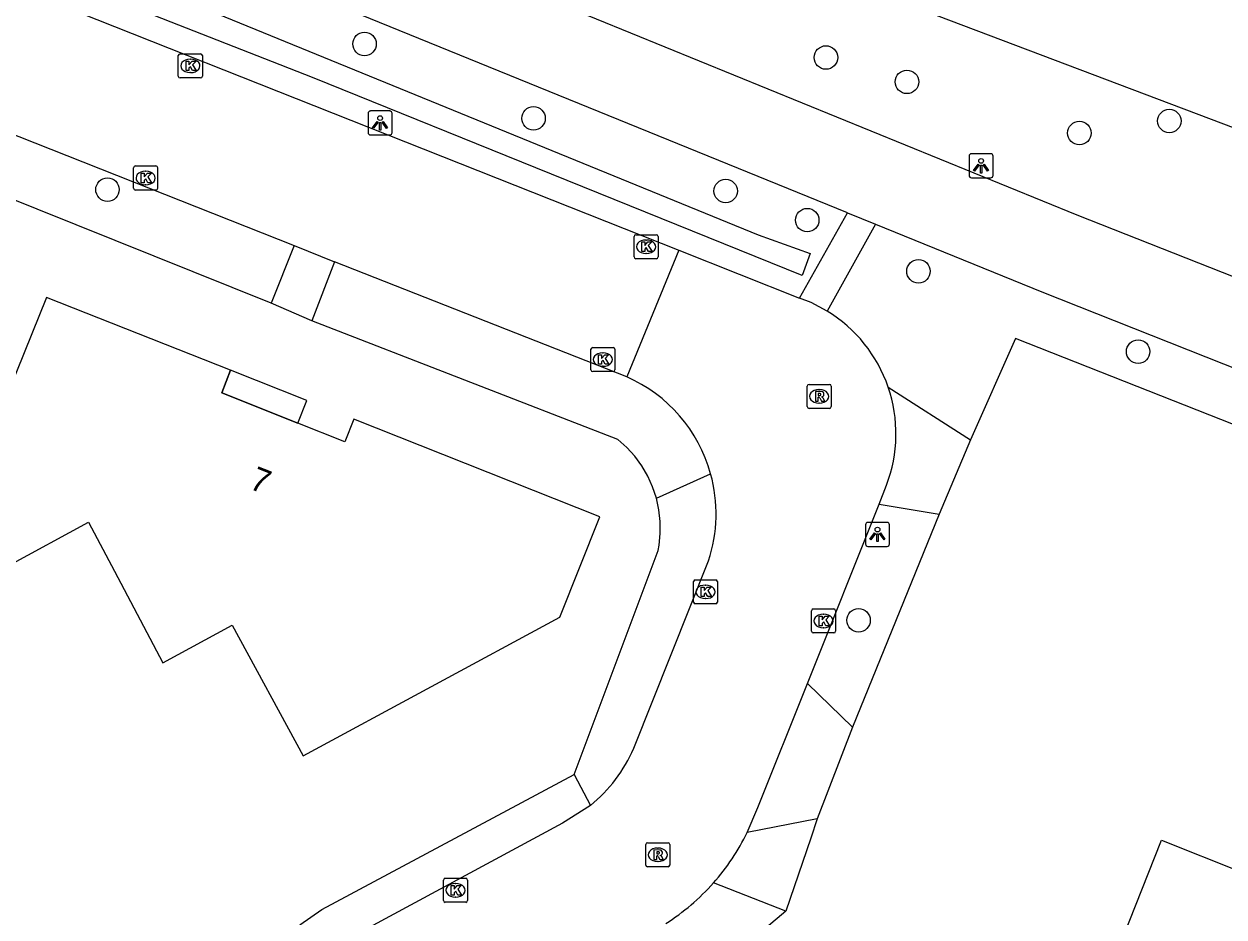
# Model space of a CAD drawing. Extents: x 157321 to 158827, y 386650 to 388532.
# Drawn here: x 158189.75 to 158239.72, y 387285.73 to 387322.9 of the extents above; entities that cross this region are included whole.
import ezdxf

# ---------------------------------------------------------------- set-up
doc = ezdxf.new("R2010")
doc.units = 0
for name, color, linetype in [('IMGEO_Berm_groen', 7, 'Continuous'), ('IMGEO_Boom', 7, 'Continuous'), ('IMGEO_Fietspad_gesloten', 7, 'Continuous'), ('IMGEO_Fietspad_halfverhard', 7, 'Continuous'), ('IMGEO_Greppel_droge_sloot', 7, 'Continuous'), ('IMGEO_Groenvoorziening', 7, 'Continuous'), ('IMGEO_Kolk', 7, 'Continuous'), ('IMGEO_Lichtpunt', 7, 'Continuous'), ('IMGEO_Pand', 7, 'Continuous'), ('IMGEO_Pand_nummerreeks', 7, 'Continuous'), ('IMGEO_Pand_overbouw', 7, 'Continuous'), ('IMGEO_Rijbaan_lokaal_gesloten', 7, 'Continuous'), ('IMGEO_Rioolput', 7, 'Continuous'), ('IMGEO_Voetpad_open', 7, 'Continuous')]:
    doc.layers.add(name, color=color, linetype=linetype)

msp = doc.modelspace()

# ---------------------------------------------------------------- linework, layer by layer
at = {"layer": 'IMGEO_Berm_groen'}
msp.add_lwpolyline([(158278.806, 387307.93), (158276.895, 387304.182), (158265.187, 387309.099), (158221.254, 387325.716), (158222.09, 387328.153)], dxfattribs=at)
at = {"layer": 'IMGEO_Boom'}
for centre in [(158203.934, 387322.067), (158223.145, 387321.502), (158226.519, 387320.489), (158210.971, 387318.97), (158237.443, 387318.86), (158233.699, 387318.359), (158193.23, 387316.004), (158218.971, 387315.946), (158222.367, 387314.735), (158226.999, 387312.606), (158236.145, 387309.262), (158224.505, 387298.08)]:
    msp.add_circle(centre, 0.489, dxfattribs=at)
at = {"layer": 'IMGEO_Fietspad_gesloten'}
for points in [[(158179.894, 387336.819), (158196.427, 387330.121), (158233.586, 387314.953), (158272.994, 387299.418), (158274.047, 387299.005), (158289.751, 387292.854)], [(158224.046, 387315.044), (158195.029, 387326.837), (158178.354, 387333.585)], [(158224.046, 387315.044), (158225.213, 387314.57)], [(158225.213, 387314.57), (158232.134, 387311.757), (158271.569, 387296.126), (158272.304, 387295.835), (158288.418, 387289.45)]]:
    msp.add_lwpolyline(points, dxfattribs=at)
at = {"layer": 'IMGEO_Fietspad_halfverhard'}
for points in [[(158222.051, 387311.493), (158224.046, 387315.044)], [(158225.213, 387314.57), (158223.199, 387310.95)]]:
    msp.add_lwpolyline(points, dxfattribs=at)
at = {"layer": 'IMGEO_Greppel_droge_sloot'}
msp.add_lwpolyline([(158187.304, 387327.627), (158220.325, 387314.118), (158222.485, 387313.349), (158222.156, 387312.434), (158211.722, 387316.644), (158201.765, 387320.671), (158189.611, 387325.448), (158179.141, 387329.549), (158177.31, 387330.226), (158177.749, 387331.214), (158187.304, 387327.627)], dxfattribs=at)
at = {"layer": 'IMGEO_Groenvoorziening'}
for points in [[(158200.048, 387311.279), (158172.43, 387322.36)], [(158216.085, 387303.161), (158215.93, 387303.63), (158215.727, 387304.08), (158215.478, 387304.507), (158215.186, 387304.905), (158214.854, 387305.271), (158214.486, 387305.6), (158201.742, 387310.539)], [(158267.812, 387295.314), (158231.041, 387309.802), (158229.169, 387305.594)], [(158216.085, 387303.161), (158218.345, 387304.178)], [(158212.666, 387291.668), (158216.158, 387300.99), (158216.196, 387301.202), (158216.245, 387301.693), (158216.243, 387302.187), (158216.189, 387302.678), (158216.085, 387303.161)], [(158227.86, 387302.504), (158224.25, 387293.632)], [(158222.786, 387289.814), (158222.515, 387289.017), (158221.481, 387285.976)]]:
    msp.add_lwpolyline(points, dxfattribs=at)
at = {"layer": 'IMGEO_Kolk'}
for p, q in [((158196.254, 387321.655), (158197.106, 387321.655)), ((158196.179, 387320.729), (158196.179, 387321.581)), ((158196.667, 387321.435), (158196.692, 387321.435)), ((158197.18, 387321.581), (158197.18, 387320.729)), ((158197.106, 387320.655), (158196.254, 387320.655)), ((158196.69, 387320.875), (158196.665, 387320.875)), ((158194.318, 387316.061), (158194.318, 387316.913)), ((158194.393, 387316.987), (158195.245, 387316.987)), ((158194.806, 387316.767), (158194.831, 387316.767)), ((158195.319, 387316.913), (158195.319, 387316.061)), ((158194.829, 387316.207), (158194.804, 387316.207)), ((158195.245, 387315.987), (158194.393, 387315.987)), ((158215.158, 387313.201), (158215.158, 387314.053)), ((158215.233, 387314.127), (158216.085, 387314.127)), ((158215.646, 387313.907), (158215.671, 387313.907)), ((158216.159, 387314.053), (158216.159, 387313.201)), ((158215.669, 387313.347), (158215.644, 387313.347)), ((158216.085, 387313.127), (158215.233, 387313.127)), ((158213.358, 387308.507), (158213.358, 387309.359)), ((158213.433, 387309.433), (158214.285, 387309.433)), ((158213.846, 387309.213), (158213.871, 387309.213)), ((158214.359, 387309.359), (158214.359, 387308.507)), ((158213.869, 387308.653), (158213.844, 387308.653)), ((158214.285, 387308.433), (158213.433, 387308.433)), ((158217.629, 387298.839), (158217.629, 387299.691)), ((158217.704, 387299.765), (158218.556, 387299.765)), ((158218.63, 387299.691), (158218.63, 387298.839)), ((158218.117, 387299.545), (158218.142, 387299.545)), ((158218.556, 387298.765), (158217.704, 387298.765)), ((158218.14, 387298.985), (158218.115, 387298.985)), ((158222.545, 387297.627), (158222.545, 387298.479)), ((158222.62, 387298.553), (158223.472, 387298.553)), ((158223.033, 387298.333), (158223.058, 387298.333)), ((158223.546, 387298.479), (158223.546, 387297.627)), ((158223.056, 387297.773), (158223.031, 387297.773)), ((158223.472, 387297.553), (158222.62, 387297.553)), ((158207.22, 387286.417), (158207.22, 387287.269)), ((158207.295, 387287.343), (158208.147, 387287.343)), ((158208.221, 387287.269), (158208.221, 387286.417)), ((158207.708, 387287.123), (158207.733, 387287.123)), ((158208.147, 387286.343), (158207.295, 387286.343)), ((158207.731, 387286.563), (158207.706, 387286.563))]:
    msp.add_line(p, q, dxfattribs=at)
for points in [[(158196.254, 387321.655), (158197.106, 387321.655)], [(158196.179, 387320.729), (158196.179, 387321.581)], [(158196.5, 387321.355), (158196.623, 387321.355), (158196.623, 387321.204), (158196.753, 387321.355), (158196.917, 387321.355), (158196.771, 387321.204), (158196.924, 387320.955), (158196.772, 387320.955), (158196.687, 387321.119), (158196.623, 387321.052), (158196.623, 387320.955), (158196.5, 387320.955), (158196.5, 387321.355)], [(158197.18, 387321.581), (158197.18, 387320.729)], [(158197.106, 387320.655), (158196.254, 387320.655)], [(158194.318, 387316.061), (158194.318, 387316.913)], [(158194.393, 387316.987), (158195.245, 387316.987)], [(158194.639, 387316.687), (158194.762, 387316.687), (158194.762, 387316.536), (158194.892, 387316.687), (158195.056, 387316.687), (158194.91, 387316.536), (158195.063, 387316.287), (158194.911, 387316.287), (158194.826, 387316.451), (158194.762, 387316.384), (158194.762, 387316.287), (158194.639, 387316.287), (158194.639, 387316.687)], [(158195.319, 387316.913), (158195.319, 387316.061)], [(158195.245, 387315.987), (158194.393, 387315.987)], [(158215.158, 387313.201), (158215.158, 387314.053)], [(158215.233, 387314.127), (158216.085, 387314.127)], [(158215.479, 387313.827), (158215.602, 387313.827), (158215.602, 387313.676), (158215.732, 387313.827), (158215.896, 387313.827), (158215.75, 387313.676), (158215.903, 387313.427), (158215.751, 387313.427), (158215.666, 387313.591), (158215.602, 387313.524), (158215.602, 387313.427), (158215.479, 387313.427), (158215.479, 387313.827)], [(158216.159, 387314.053), (158216.159, 387313.201)], [(158216.085, 387313.127), (158215.233, 387313.127)], [(158213.358, 387308.507), (158213.358, 387309.359)], [(158213.433, 387309.433), (158214.285, 387309.433)], [(158214.359, 387309.359), (158214.359, 387308.507)], [(158213.679, 387309.133), (158213.802, 387309.133), (158213.802, 387308.982), (158213.932, 387309.133), (158214.096, 387309.133), (158213.95, 387308.982), (158214.103, 387308.733), (158213.951, 387308.733), (158213.866, 387308.897), (158213.802, 387308.83), (158213.802, 387308.733), (158213.679, 387308.733), (158213.679, 387309.133)], [(158214.285, 387308.433), (158213.433, 387308.433)], [(158217.629, 387298.839), (158217.629, 387299.691)], [(158217.704, 387299.765), (158218.556, 387299.765)], [(158218.63, 387299.691), (158218.63, 387298.839)], [(158217.95, 387299.465), (158218.073, 387299.465), (158218.073, 387299.314), (158218.203, 387299.465), (158218.367, 387299.465), (158218.221, 387299.314), (158218.374, 387299.065), (158218.222, 387299.065), (158218.137, 387299.229), (158218.073, 387299.162), (158218.073, 387299.065), (158217.95, 387299.065), (158217.95, 387299.465)], [(158218.556, 387298.765), (158217.704, 387298.765)], [(158222.545, 387297.627), (158222.545, 387298.479)], [(158222.62, 387298.553), (158223.472, 387298.553)], [(158222.866, 387298.253), (158222.989, 387298.253), (158222.989, 387298.102), (158223.119, 387298.253), (158223.283, 387298.253), (158223.137, 387298.102), (158223.29, 387297.853), (158223.138, 387297.853), (158223.053, 387298.017), (158222.989, 387297.95), (158222.989, 387297.853), (158222.866, 387297.853), (158222.866, 387298.253)], [(158223.546, 387298.479), (158223.546, 387297.627)], [(158223.472, 387297.553), (158222.62, 387297.553)], [(158207.22, 387286.417), (158207.22, 387287.269)], [(158207.295, 387287.343), (158208.147, 387287.343)], [(158208.221, 387287.269), (158208.221, 387286.417)], [(158207.541, 387287.043), (158207.664, 387287.043), (158207.664, 387286.892), (158207.794, 387287.043), (158207.958, 387287.043), (158207.812, 387286.892), (158207.965, 387286.643), (158207.813, 387286.643), (158207.728, 387286.807), (158207.664, 387286.74), (158207.664, 387286.643), (158207.541, 387286.643), (158207.541, 387287.043)], [(158208.147, 387286.343), (158207.295, 387286.343)]]:
    msp.add_lwpolyline(points, dxfattribs=at)
for centre, start, end in [((158196.256, 387321.579), 91.552, 178.448), ((158196.256, 387321.579), 91.552, 178.448), ((158197.104, 387321.579), 1.552, 88.448), ((158197.104, 387321.579), 1.552, 88.448), ((158196.256, 387320.731), 181.552, 268.448), ((158196.256, 387320.731), 181.552, 268.448), ((158197.104, 387320.731), 271.552, 358.448), ((158197.104, 387320.731), 271.552, 358.448), ((158194.395, 387316.911), 91.552, 178.448), ((158194.395, 387316.911), 91.552, 178.448), ((158195.243, 387316.911), 1.552, 88.448), ((158195.243, 387316.911), 1.552, 88.448), ((158194.395, 387316.063), 181.552, 268.448), ((158194.395, 387316.063), 181.552, 268.448), ((158195.243, 387316.063), 271.552, 358.448), ((158195.243, 387316.063), 271.552, 358.448), ((158215.235, 387314.051), 91.552, 178.448), ((158215.235, 387314.051), 91.552, 178.448), ((158216.083, 387314.051), 1.552, 88.448), ((158216.083, 387314.051), 1.552, 88.448), ((158215.235, 387313.203), 181.552, 268.448), ((158215.235, 387313.203), 181.552, 268.448), ((158216.083, 387313.203), 271.552, 358.448), ((158216.083, 387313.203), 271.552, 358.448), ((158213.435, 387309.357), 91.552, 178.448), ((158213.435, 387309.357), 91.552, 178.448), ((158214.283, 387309.357), 1.552, 88.448), ((158214.283, 387309.357), 1.552, 88.448), ((158213.435, 387308.509), 181.552, 268.448), ((158213.435, 387308.509), 181.552, 268.448), ((158214.283, 387308.509), 271.552, 358.448), ((158214.283, 387308.509), 271.552, 358.448), ((158217.706, 387299.689), 91.552, 178.448), ((158217.706, 387299.689), 91.552, 178.448), ((158218.554, 387299.689), 1.552, 88.448), ((158218.554, 387299.689), 1.552, 88.448), ((158217.706, 387298.841), 181.552, 268.448), ((158217.706, 387298.841), 181.552, 268.448), ((158218.554, 387298.841), 271.552, 358.448), ((158218.554, 387298.841), 271.552, 358.448), ((158222.622, 387298.477), 91.552, 178.448), ((158222.622, 387298.477), 91.552, 178.448), ((158223.47, 387298.477), 1.552, 88.448), ((158223.47, 387298.477), 1.552, 88.448), ((158222.622, 387297.629), 181.552, 268.448), ((158222.622, 387297.629), 181.552, 268.448), ((158223.47, 387297.629), 271.552, 358.448), ((158223.47, 387297.629), 271.552, 358.448), ((158207.297, 387287.267), 91.552, 178.448), ((158207.297, 387287.267), 91.552, 178.448), ((158208.145, 387287.267), 1.552, 88.448), ((158208.145, 387287.267), 1.552, 88.448), ((158207.297, 387286.419), 181.552, 268.448), ((158207.297, 387286.419), 181.552, 268.448), ((158208.145, 387286.419), 271.552, 358.448), ((158208.145, 387286.419), 271.552, 358.448)]:
    msp.add_arc(centre, 0.0765, start, end, dxfattribs=at)
for centre, major_axis, ratio, start_param, end_param in [((158196.666, 387321.155), (-0.387, 0.002), 0.722429, 4.712389, 7.853982), ((158196.691, 387321.155), (-0.39, 0.002), 0.717154, 1.570796, 4.712389), ((158194.805, 387316.487), (-0.387, 0.002), 0.722429, 4.712389, 7.853982), ((158194.83, 387316.487), (-0.39, 0.002), 0.717154, 1.570796, 4.712389), ((158215.645, 387313.627), (-0.387, 0.002), 0.722429, 4.712389, 7.853982), ((158215.67, 387313.627), (-0.39, 0.002), 0.717154, 1.570796, 4.712389), ((158213.845, 387308.933), (-0.387, 0.002), 0.722429, 4.712389, 7.853982), ((158213.87, 387308.933), (-0.39, 0.002), 0.717154, 1.570796, 4.712389), ((158218.116, 387299.265), (-0.387, 0.002), 0.722429, 4.712389, 7.853982), ((158218.141, 387299.265), (-0.39, 0.002), 0.717154, 1.570796, 4.712389), ((158223.032, 387298.053), (-0.387, 0.002), 0.722429, 4.712389, 7.853982), ((158223.057, 387298.053), (-0.39, 0.002), 0.717154, 1.570796, 4.712389), ((158207.707, 387286.843), (-0.387, 0.002), 0.722429, 4.712389, 7.853982), ((158207.732, 387286.843), (-0.39, 0.002), 0.717154, 1.570796, 4.712389)]:
    msp.add_ellipse(centre, major_axis=major_axis, ratio=ratio, start_param=start_param, end_param=end_param, dxfattribs=at)
at = {"layer": 'IMGEO_Lichtpunt'}
for p, q in [((158204.082, 387319.181), (158204.082, 387318.374)), ((158204.082, 387319.181), (158204.082, 387318.374)), ((158204.984, 387319.276), (158204.176, 387319.276)), ((158204.984, 387319.276), (158204.176, 387319.276)), ((158205.078, 387318.374), (158205.078, 387319.181)), ((158205.078, 387318.374), (158205.078, 387319.181)), ((158204.176, 387318.28), (158204.984, 387318.28)), ((158204.176, 387318.28), (158204.984, 387318.28)), ((158229.107, 387317.401), (158229.107, 387316.594)), ((158229.107, 387317.401), (158229.107, 387316.594)), ((158230.009, 387317.496), (158229.201, 387317.496)), ((158230.009, 387317.496), (158229.201, 387317.496)), ((158230.103, 387316.594), (158230.103, 387317.401)), ((158230.103, 387316.594), (158230.103, 387317.401)), ((158229.201, 387316.5), (158230.009, 387316.5)), ((158229.201, 387316.5), (158230.009, 387316.5)), ((158225.695, 387302.154), (158224.887, 387302.154)), ((158225.695, 387302.154), (158224.887, 387302.154)), ((158224.793, 387302.059), (158224.793, 387301.252)), ((158224.793, 387302.059), (158224.793, 387301.252)), ((158225.789, 387301.252), (158225.789, 387302.059)), ((158225.789, 387301.252), (158225.789, 387302.059)), ((158224.887, 387301.158), (158225.695, 387301.158)), ((158224.887, 387301.158), (158225.695, 387301.158))]:
    msp.add_line(p, q, dxfattribs=at)
for points in [[(158204.456, 387318.845), (158204.495, 387318.817), (158204.307, 387318.555), (158204.269, 387318.582), (158204.456, 387318.845)], [(158204.558, 387318.797), (158204.605, 387318.797), (158204.605, 387318.475), (158204.558, 387318.475), (158204.558, 387318.797)], [(158204.668, 387318.817), (158204.706, 387318.844), (158204.893, 387318.582), (158204.854, 387318.554), (158204.668, 387318.817)], [(158229.481, 387317.065), (158229.52, 387317.037), (158229.332, 387316.775), (158229.294, 387316.802), (158229.481, 387317.065)], [(158229.583, 387317.017), (158229.63, 387317.017), (158229.63, 387316.695), (158229.583, 387316.695), (158229.583, 387317.017)], [(158229.693, 387317.037), (158229.731, 387317.064), (158229.918, 387316.802), (158229.879, 387316.774), (158229.693, 387317.037)], [(158225.167, 387301.723), (158225.206, 387301.695), (158225.018, 387301.433), (158224.98, 387301.46), (158225.167, 387301.723)], [(158225.269, 387301.675), (158225.316, 387301.675), (158225.316, 387301.353), (158225.269, 387301.353), (158225.269, 387301.675)], [(158225.379, 387301.695), (158225.417, 387301.722), (158225.604, 387301.46), (158225.565, 387301.432), (158225.379, 387301.695)]]:
    msp.add_lwpolyline(points, dxfattribs=at)
for centre in [(158204.581, 387318.979), (158229.606, 387317.199), (158225.292, 387301.857)]:
    msp.add_circle(centre, 0.0994, dxfattribs=at)
for centre, start, end in [((158204.176, 387319.181), 90, 180), ((158204.176, 387319.181), 90, 180), ((158204.984, 387319.181), 0, 90), ((158204.984, 387319.181), 0, 90), ((158204.176, 387318.374), 180, 270), ((158204.176, 387318.374), 180, 270), ((158204.984, 387318.374), 270, 0), ((158204.984, 387318.374), 270, 360), ((158229.201, 387317.401), 90, 180), ((158229.201, 387317.401), 90, 180), ((158230.009, 387317.401), 0, 90), ((158230.009, 387317.401), 0, 90), ((158229.201, 387316.594), 180, 270), ((158229.201, 387316.594), 180, 270), ((158230.009, 387316.594), 270, 0), ((158230.009, 387316.594), 270, 360), ((158224.887, 387302.059), 90, 180), ((158224.887, 387302.059), 90, 180), ((158225.695, 387302.059), 0, 90), ((158225.695, 387302.059), 0, 90), ((158224.887, 387301.252), 180, 270), ((158224.887, 387301.252), 180, 270), ((158225.695, 387301.252), 270, 0), ((158225.695, 387301.252), 270, 360)]:
    msp.add_arc(centre, 0.0946, start, end, dxfattribs=at)
at = {"layer": 'IMGEO_Pand'}
for points in [[(158203.483, 387306.446), (158203.112, 387305.513), (158201.15, 387306.291), (158197.986, 387307.545), (158198.358, 387308.486), (158190.685, 387311.518), (158189.153, 387307.696), (158185.52, 387305.721), (158186.728, 387303.535), (158186.195, 387303.228), (158186.474, 387302.714), (158187.529, 387303.287), (158189.116, 387300.367), (158192.433, 387302.167), (158193.515, 387300.122), (158195.529, 387296.309), (158198.42, 387297.878), (158201.372, 387292.438), (158212.072, 387298.205), (158213.734, 387302.382), (158203.483, 387306.446)], [(158237.116, 387288.93), (158240.464, 387287.604), (158244.111, 387296.805), (158249.488, 387294.684), (158250.355, 387295.05), (158251.933, 387294.404), (158252.607, 387292.838), (158251.998, 387291.256), (158251.148, 387290.862), (158246.289, 387278.719), (158242.857, 387280.086), (158238.212, 387281.937), (158238.581, 387282.865), (158235.239, 387284.197), (158237.116, 387288.93)]]:
    msp.add_lwpolyline(points, dxfattribs=at)
at = {"layer": 'IMGEO_Pand_overbouw'}
msp.add_lwpolyline([(158201.15, 387306.291), (158201.524, 387307.233), (158198.358, 387308.486), (158197.986, 387307.545)], close=True, dxfattribs=at)
at = {"layer": 'IMGEO_Rijbaan_lokaal_gesloten'}
for points in [[(158177.571, 387329.112), (158217.018, 387313.487)], [(158173.33, 387324.641), (158201.008, 387313.673)], [(158201.008, 387313.673), (158202.682, 387313.005)], [(158217.018, 387313.487), (158214.851, 387308.211)], [(158217.018, 387313.487), (158222.051, 387311.493)], [(158214.851, 387308.211), (158202.682, 387313.005)], [(158223.199, 387310.95), (158222.531, 387311.303), (158222.051, 387311.493)], [(158225.358, 387302.918), (158225.666, 387303.699)], [(158222.375, 387295.445), (158225.358, 387302.918)], [(158215.147, 387292.757), (158218.253, 387300.556)], [(158219.872, 387289.252), (158220.307, 387290.283), (158222.375, 387295.445)], [(158213.337, 387290.375), (158212.181, 387289.632), (158203.049, 387284.719), (158202.098, 387284.23)]]:
    msp.add_lwpolyline(points, dxfattribs=at)
for centre, radius, start, end in [((158220.075, 387305.844), 5.986, 18.9435, 58.5438), ((158212.351, 387302.515), 6.221, 15.5066, 66.3016), ((158220.07, 387305.841), 5.991, 339.0548, 18.9552), ((158212.361, 387302.518), 6.21, 341.5853, 15.5046), ((158209.36, 387295.276), 6.312, 309.0614, 336.4787), ((158211.31, 387293.478), 9.548, 318.4893, 333.7289), ((158211.357, 387293.453), 9.496, 302.6484, 318.4158)]:
    msp.add_arc(centre, radius, start, end, dxfattribs=at)
at = {"layer": 'IMGEO_Rioolput'}
for p, q in [((158222.367, 387306.974), (158222.367, 387307.826)), ((158222.442, 387307.9), (158223.294, 387307.9)), ((158222.855, 387307.68), (158222.88, 387307.68)), ((158223.368, 387307.826), (158223.368, 387306.974)), ((158223.294, 387306.9), (158222.442, 387306.9)), ((158222.878, 387307.12), (158222.853, 387307.12)), ((158215.644, 387287.895), (158215.644, 387288.747)), ((158215.719, 387288.821), (158216.571, 387288.821)), ((158216.645, 387288.747), (158216.645, 387287.895)), ((158216.132, 387288.601), (158216.157, 387288.601)), ((158216.571, 387287.821), (158215.719, 387287.821)), ((158216.155, 387288.041), (158216.13, 387288.041))]:
    msp.add_line(p, q, dxfattribs=at)
for points in [[(158222.367, 387306.974), (158222.367, 387307.826)], [(158222.442, 387307.9), (158223.294, 387307.9)], [(158223.368, 387307.826), (158223.368, 387306.974)], [(158222.956, 387307.598), (158222.704, 387307.6), (158222.704, 387307.2)], [(158222.704, 387307.2), (158222.828, 387307.2), (158222.828, 387307.362), (158222.839, 387307.362)], [(158222.882, 387307.519), (158222.828, 387307.519), (158222.828, 387307.438)], [(158222.828, 387307.438), (158222.88, 387307.438)], [(158222.886, 387307.333), (158222.957, 387307.2), (158223.097, 387307.2), (158223.032, 387307.326)], [(158223.294, 387306.9), (158222.442, 387306.9)], [(158215.644, 387287.895), (158215.644, 387288.747)], [(158215.719, 387288.821), (158216.571, 387288.821)], [(158216.645, 387288.747), (158216.645, 387287.895)], [(158216.233, 387288.519), (158215.981, 387288.521), (158215.981, 387288.121)], [(158215.981, 387288.121), (158216.105, 387288.121), (158216.105, 387288.283), (158216.116, 387288.283)], [(158216.159, 387288.44), (158216.105, 387288.44), (158216.105, 387288.359)], [(158216.105, 387288.359), (158216.157, 387288.359)], [(158216.163, 387288.254), (158216.234, 387288.121), (158216.374, 387288.121), (158216.309, 387288.247)], [(158216.571, 387287.821), (158215.719, 387287.821)]]:
    msp.add_lwpolyline(points, dxfattribs=at)
for centre, radius, start, end in [((158222.444, 387307.824), 0.0765, 91.552, 178.448), ((158222.444, 387307.824), 0.0765, 91.552, 178.448), ((158223.292, 387307.824), 0.0765, 1.552, 88.448), ((158223.292, 387307.824), 0.0765, 1.552, 88.448), ((158222.838, 387307.309), 0.0533, 26.0293, 88.6989), ((158222.864, 387307.627), 0.19, 274.7715, 282.9687), ((158222.888, 387307.423), 0.0964, 77.0061, 93.1865), ((158222.902, 387307.48), 0.0378, 276.6634, 79.6772), ((158222.955, 387307.488), 0.109, 350.3612, 89.416), ((158222.953, 387307.488), 0.112, 277.5842, 350.9817), ((158222.937, 387307.273), 0.108, 29.5134, 73.7905), ((158222.444, 387306.976), 0.0765, 181.552, 268.448), ((158222.444, 387306.976), 0.0765, 181.552, 268.448), ((158223.292, 387306.976), 0.0765, 271.552, 358.448), ((158223.292, 387306.976), 0.0765, 271.552, 358.448), ((158215.721, 387288.745), 0.0765, 91.552, 178.448), ((158215.721, 387288.745), 0.0765, 91.552, 178.448), ((158216.569, 387288.745), 0.0765, 1.552, 88.448), ((158216.569, 387288.745), 0.0765, 1.552, 88.448), ((158216.115, 387288.23), 0.0533, 26.0293, 88.6989), ((158216.141, 387288.548), 0.19, 274.7715, 282.9687), ((158216.165, 387288.344), 0.0964, 77.0061, 93.1865), ((158216.179, 387288.401), 0.0378, 276.6634, 79.6772), ((158216.232, 387288.409), 0.109, 350.3612, 89.416), ((158216.23, 387288.409), 0.112, 277.5842, 350.9817), ((158216.214, 387288.194), 0.108, 29.5134, 73.7905), ((158215.721, 387287.897), 0.0765, 181.552, 268.448), ((158215.721, 387287.897), 0.0765, 181.552, 268.448), ((158216.569, 387287.897), 0.0765, 271.552, 358.448), ((158216.569, 387287.897), 0.0765, 271.552, 358.448)]:
    msp.add_arc(centre, radius, start, end, dxfattribs=at)
for centre, major_axis, ratio, start_param, end_param in [((158222.854, 387307.4), (-0.387, 0.002), 0.722429, 4.712389, 7.853982), ((158222.879, 387307.4), (-0.39, 0.002), 0.717154, 1.570796, 4.712389), ((158216.131, 387288.321), (-0.387, 0.002), 0.722429, 4.712389, 7.853982), ((158216.156, 387288.321), (-0.39, 0.002), 0.717154, 1.570796, 4.712389)]:
    msp.add_ellipse(centre, major_axis=major_axis, ratio=ratio, start_param=start_param, end_param=end_param, dxfattribs=at)
at = {"layer": 'IMGEO_Voetpad_open'}
for points in [[(158201.008, 387313.673), (158200.048, 387311.279)], [(158202.682, 387313.005), (158201.742, 387310.539)], [(158201.742, 387310.539), (158200.048, 387311.279)], [(158225.737, 387307.787), (158229.169, 387305.594)], [(158229.169, 387305.594), (158227.86, 387302.504)], [(158225.358, 387302.918), (158227.86, 387302.504)], [(158224.25, 387293.632), (158222.375, 387295.445)], [(158224.25, 387293.632), (158222.786, 387289.814)], [(158201.235, 387285.4), (158202.158, 387286.046), (158212.666, 387291.668)], [(158212.666, 387291.668), (158213.337, 387290.375)], [(158222.786, 387289.814), (158219.872, 387289.252)], [(158221.481, 387285.976), (158218.46, 387287.15)], [(158221.481, 387285.976), (158218.078, 387283.103)]]:
    msp.add_lwpolyline(points, dxfattribs=at)

# ---------------------------------------------------------------- texts
at = {"layer": 'IMGEO_Pand_nummerreeks'}
msp.add_text('7', height=1, rotation=338.3766, dxfattribs=at).set_placement((158199.084, 387303.582))

doc.saveas('drawing.dxf')
